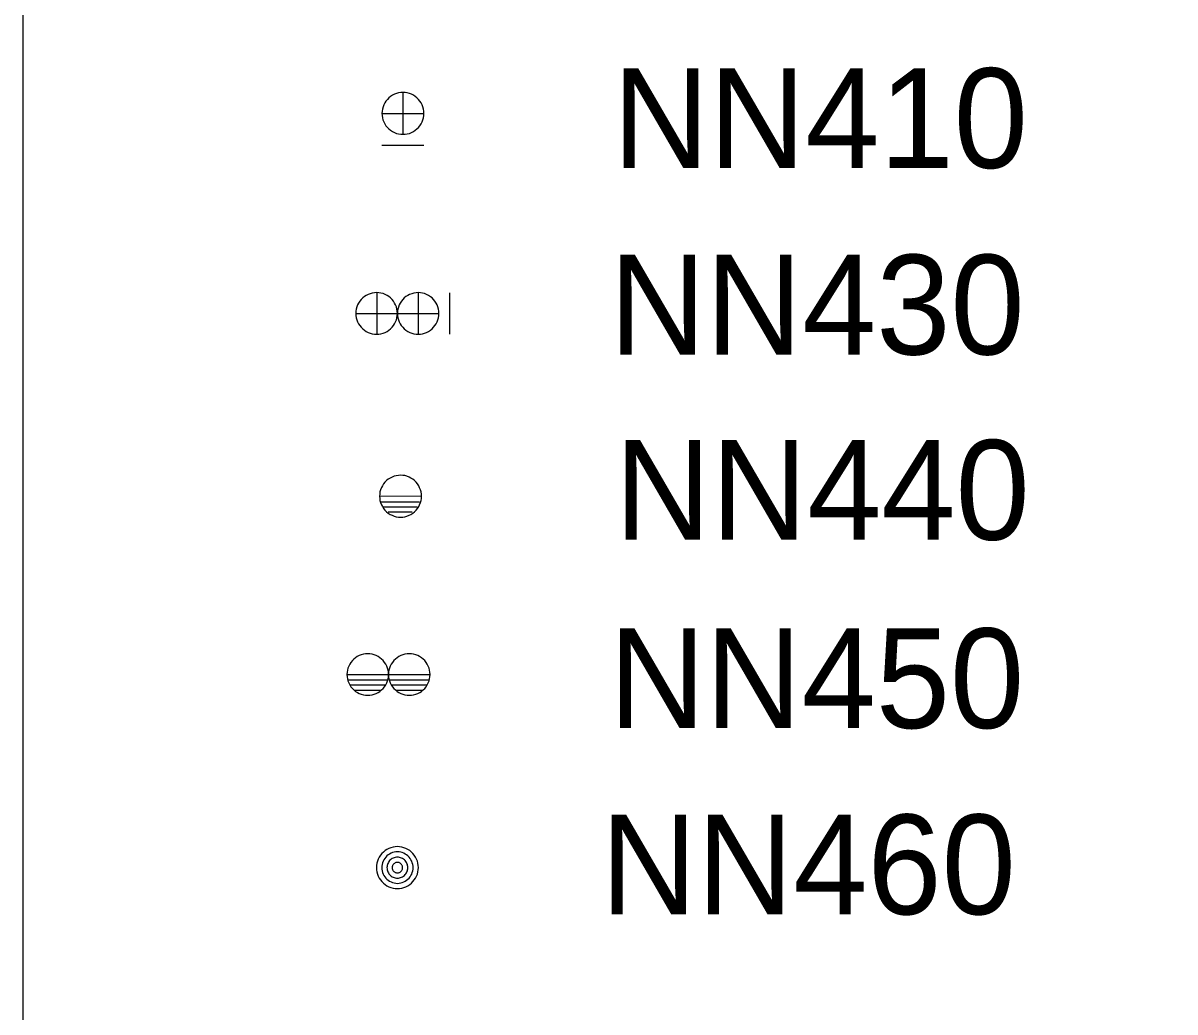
# Model space of a CAD drawing. Extents: x -592825 to -592404, y -1153473 to -1153230.
# Drawn here: x -592679.08 to -592661.76, y -1153367.06 to -1153352.19 of the extents above; entities that cross this region are included whole.
import ezdxf

# ---------------------------------------------------------------- set-up
doc = ezdxf.new("R2010")
doc.units = 0
doc.layers.add('Vrstva 43', color=7, linetype='Continuous')
doc.layers.add('Vrstva 63', color=7, linetype='Continuous')

msp = doc.modelspace()

# ---------------------------------------------------------------- linework, layer by layer
at = {"layer": 'Vrstva 43'}
for points in [[(-592673.055, -1153353.548), (-592673.057, -1153353.515), (-592673.061, -1153353.483), (-592673.07, -1153353.45), (-592673.082, -1153353.42), (-592673.097, -1153353.39), (-592673.115, -1153353.362), (-592673.135, -1153353.337), (-592673.159, -1153353.314), (-592673.185, -1153353.293), (-592673.213, -1153353.275), (-592673.241, -1153353.26), (-592673.273, -1153353.248), (-592673.305, -1153353.24), (-592673.337, -1153353.234), (-592673.37, -1153353.233), (-592673.403, -1153353.235), (-592673.435, -1153353.24), (-592673.467, -1153353.248), (-592673.498, -1153353.26), (-592673.527, -1153353.275), (-592673.555, -1153353.293), (-592673.581, -1153353.314), (-592673.604, -1153353.337), (-592673.625, -1153353.362), (-592673.643, -1153353.391), (-592673.657, -1153353.42), (-592673.669, -1153353.45), (-592673.678, -1153353.483), (-592673.683, -1153353.515), (-592673.685, -1153353.548), (-592673.683, -1153353.581), (-592673.678, -1153353.614), (-592673.67, -1153353.646), (-592673.657, -1153353.676), (-592673.643, -1153353.706), (-592673.625, -1153353.733), (-592673.604, -1153353.759), (-592673.581, -1153353.782), (-592673.555, -1153353.802), (-592673.527, -1153353.82), (-592673.498, -1153353.836), (-592673.467, -1153353.848), (-592673.435, -1153353.856), (-592673.403, -1153353.861), (-592673.37, -1153353.862), (-592673.337, -1153353.861), (-592673.305, -1153353.856), (-592673.273, -1153353.848), (-592673.241, -1153353.836), (-592673.213, -1153353.82), (-592673.185, -1153353.802), (-592673.159, -1153353.782), (-592673.135, -1153353.758), (-592673.115, -1153353.734), (-592673.097, -1153353.705), (-592673.082, -1153353.676), (-592673.07, -1153353.645), (-592673.061, -1153353.613), (-592673.057, -1153353.58), (-592673.055, -1153353.548)], [(-592673.371, -1153353.232), (-592673.371, -1153353.862)], [(-592673.687, -1153353.547), (-592673.056, -1153353.548)], [(-592673.686, -1153354.025), (-592673.056, -1153354.024)], [(-592673.453, -1153356.556), (-592673.455, -1153356.523), (-592673.46, -1153356.49), (-592673.469, -1153356.459), (-592673.481, -1153356.429), (-592673.495, -1153356.4), (-592673.513, -1153356.372), (-592673.534, -1153356.346), (-592673.557, -1153356.324), (-592673.582, -1153356.303), (-592673.609, -1153356.285), (-592673.639, -1153356.27), (-592673.669, -1153356.258), (-592673.701, -1153356.25), (-592673.733, -1153356.246), (-592673.765, -1153356.243), (-592673.799, -1153356.246), (-592673.831, -1153356.25), (-592673.863, -1153356.259), (-592673.893, -1153356.27), (-592673.922, -1153356.286), (-592673.949, -1153356.303), (-592673.975, -1153356.324), (-592673.998, -1153356.347), (-592674.019, -1153356.372), (-592674.036, -1153356.4), (-592674.051, -1153356.428), (-592674.063, -1153356.459), (-592674.071, -1153356.491), (-592674.077, -1153356.523), (-592674.079, -1153356.556), (-592674.077, -1153356.588), (-592674.071, -1153356.62), (-592674.063, -1153356.652), (-592674.051, -1153356.684), (-592674.036, -1153356.712), (-592674.019, -1153356.739), (-592673.998, -1153356.764), (-592673.975, -1153356.788), (-592673.949, -1153356.808), (-592673.921, -1153356.826), (-592673.893, -1153356.841), (-592673.863, -1153356.852), (-592673.831, -1153356.862), (-592673.799, -1153356.866), (-592673.765, -1153356.868), (-592673.733, -1153356.867), (-592673.701, -1153356.862), (-592673.669, -1153356.853), (-592673.639, -1153356.841), (-592673.609, -1153356.826), (-592673.583, -1153356.808), (-592673.557, -1153356.788), (-592673.534, -1153356.765), (-592673.513, -1153356.74), (-592673.495, -1153356.712), (-592673.48, -1153356.683), (-592673.469, -1153356.652), (-592673.46, -1153356.621), (-592673.455, -1153356.589), (-592673.453, -1153356.556)], [(-592673.763, -1153356.246), (-592673.763, -1153356.866)], [(-592672.828, -1153356.556), (-592672.83, -1153356.523), (-592672.835, -1153356.491), (-592672.844, -1153356.459), (-592672.855, -1153356.429), (-592672.87, -1153356.4), (-592672.888, -1153356.372), (-592672.909, -1153356.346), (-592672.931, -1153356.324), (-592672.957, -1153356.304), (-592672.985, -1153356.286), (-592673.014, -1153356.27), (-592673.044, -1153356.258), (-592673.076, -1153356.25), (-592673.108, -1153356.246), (-592673.141, -1153356.243), (-592673.173, -1153356.246), (-592673.205, -1153356.25), (-592673.237, -1153356.259), (-592673.269, -1153356.27), (-592673.297, -1153356.286), (-592673.324, -1153356.303), (-592673.349, -1153356.324), (-592673.373, -1153356.347), (-592673.393, -1153356.372), (-592673.411, -1153356.4), (-592673.427, -1153356.429), (-592673.437, -1153356.46), (-592673.447, -1153356.49), (-592673.451, -1153356.523), (-592673.453, -1153356.556), (-592673.452, -1153356.589), (-592673.447, -1153356.621), (-592673.437, -1153356.652), (-592673.426, -1153356.684), (-592673.411, -1153356.712), (-592673.394, -1153356.74), (-592673.373, -1153356.764), (-592673.35, -1153356.788), (-592673.324, -1153356.808), (-592673.297, -1153356.826), (-592673.267, -1153356.842), (-592673.237, -1153356.852), (-592673.206, -1153356.862), (-592673.173, -1153356.866), (-592673.141, -1153356.868), (-592673.108, -1153356.866), (-592673.075, -1153356.862), (-592673.044, -1153356.853), (-592673.014, -1153356.842), (-592672.985, -1153356.826), (-592672.957, -1153356.809), (-592672.931, -1153356.788), (-592672.909, -1153356.765), (-592672.888, -1153356.74), (-592672.871, -1153356.712), (-592672.855, -1153356.683), (-592672.843, -1153356.652), (-592672.835, -1153356.621), (-592672.83, -1153356.589), (-592672.828, -1153356.556)], [(-592673.143, -1153356.246), (-592673.143, -1153356.866)], [(-592672.671, -1153356.246), (-592672.671, -1153356.866)], [(-592674.079, -1153356.556), (-592672.828, -1153356.556)], [(-592673.091, -1153359.305), (-592673.093, -1153359.272), (-592673.098, -1153359.24), (-592673.107, -1153359.208), (-592673.119, -1153359.177), (-592673.133, -1153359.147), (-592673.151, -1153359.12), (-592673.172, -1153359.094), (-592673.195, -1153359.071), (-592673.221, -1153359.05), (-592673.249, -1153359.032), (-592673.278, -1153359.017), (-592673.309, -1153359.005), (-592673.341, -1153358.996), (-592673.373, -1153358.992), (-592673.407, -1153358.99), (-592673.439, -1153358.992), (-592673.471, -1153358.997), (-592673.503, -1153359.005), (-592673.534, -1153359.018), (-592673.563, -1153359.032), (-592673.591, -1153359.05), (-592673.617, -1153359.071), (-592673.641, -1153359.094), (-592673.661, -1153359.12), (-592673.679, -1153359.147), (-592673.694, -1153359.176), (-592673.705, -1153359.208), (-592673.715, -1153359.239), (-592673.719, -1153359.272), (-592673.721, -1153359.305), (-592673.719, -1153359.338), (-592673.715, -1153359.37), (-592673.705, -1153359.402), (-592673.694, -1153359.434), (-592673.679, -1153359.462), (-592673.661, -1153359.49), (-592673.641, -1153359.516), (-592673.617, -1153359.539), (-592673.591, -1153359.56), (-592673.564, -1153359.578), (-592673.534, -1153359.592), (-592673.503, -1153359.604), (-592673.471, -1153359.613), (-592673.439, -1153359.618), (-592673.406, -1153359.62), (-592673.373, -1153359.618), (-592673.341, -1153359.613), (-592673.309, -1153359.604), (-592673.278, -1153359.592), (-592673.249, -1153359.578), (-592673.221, -1153359.56), (-592673.195, -1153359.538), (-592673.172, -1153359.516), (-592673.151, -1153359.49), (-592673.133, -1153359.462), (-592673.119, -1153359.433), (-592673.107, -1153359.402), (-592673.098, -1153359.37), (-592673.093, -1153359.338), (-592673.091, -1153359.305)], [(-592673.723, -1153359.302), (-592673.092, -1153359.303)], [(-592673.707, -1153359.392), (-592673.122, -1153359.391)], [(-592673.663, -1153359.466), (-592673.156, -1153359.465)], [(-592673.594, -1153359.54), (-592673.23, -1153359.54)], [(-592673.587, -1153361.987), (-592673.589, -1153361.954), (-592673.594, -1153361.922), (-592673.603, -1153361.89), (-592673.614, -1153361.86), (-592673.629, -1153361.83), (-592673.647, -1153361.804), (-592673.667, -1153361.778), (-592673.691, -1153361.755), (-592673.716, -1153361.734), (-592673.743, -1153361.716), (-592673.773, -1153361.702), (-592673.803, -1153361.69), (-592673.835, -1153361.682), (-592673.867, -1153361.676), (-592673.899, -1153361.674), (-592673.933, -1153361.676), (-592673.965, -1153361.682), (-592673.996, -1153361.69), (-592674.027, -1153361.702), (-592674.056, -1153361.716), (-592674.083, -1153361.734), (-592674.109, -1153361.755), (-592674.131, -1153361.778), (-592674.153, -1153361.804), (-592674.17, -1153361.831), (-592674.185, -1153361.86), (-592674.197, -1153361.89), (-592674.205, -1153361.922), (-592674.211, -1153361.954), (-592674.212, -1153361.987), (-592674.211, -1153362.02), (-592674.205, -1153362.052), (-592674.197, -1153362.084), (-592674.185, -1153362.114), (-592674.17, -1153362.144), (-592674.153, -1153362.17), (-592674.131, -1153362.196), (-592674.109, -1153362.219), (-592674.083, -1153362.24), (-592674.055, -1153362.258), (-592674.027, -1153362.272), (-592673.996, -1153362.284), (-592673.965, -1153362.293), (-592673.933, -1153362.298), (-592673.899, -1153362.3), (-592673.867, -1153362.298), (-592673.835, -1153362.293), (-592673.803, -1153362.284), (-592673.773, -1153362.272), (-592673.743, -1153362.258), (-592673.716, -1153362.24), (-592673.691, -1153362.219), (-592673.667, -1153362.196), (-592673.647, -1153362.17), (-592673.629, -1153362.143), (-592673.614, -1153362.114), (-592673.603, -1153362.084), (-592673.594, -1153362.052), (-592673.589, -1153362.02), (-592673.587, -1153361.987)], [(-592672.962, -1153361.987), (-592672.964, -1153361.954), (-592672.969, -1153361.922), (-592672.977, -1153361.89), (-592672.989, -1153361.86), (-592673.004, -1153361.83), (-592673.022, -1153361.804), (-592673.043, -1153361.778), (-592673.065, -1153361.755), (-592673.091, -1153361.734), (-592673.119, -1153361.716), (-592673.147, -1153361.702), (-592673.178, -1153361.69), (-592673.209, -1153361.682), (-592673.242, -1153361.676), (-592673.275, -1153361.674), (-592673.307, -1153361.676), (-592673.339, -1153361.682), (-592673.371, -1153361.69), (-592673.402, -1153361.702), (-592673.431, -1153361.716), (-592673.458, -1153361.734), (-592673.483, -1153361.755), (-592673.507, -1153361.778), (-592673.527, -1153361.804), (-592673.545, -1153361.831), (-592673.56, -1153361.86), (-592673.571, -1153361.89), (-592673.581, -1153361.922), (-592673.585, -1153361.954), (-592673.587, -1153361.987), (-592673.585, -1153362.02), (-592673.581, -1153362.052), (-592673.571, -1153362.084), (-592673.56, -1153362.114), (-592673.545, -1153362.144), (-592673.527, -1153362.17), (-592673.507, -1153362.196), (-592673.483, -1153362.219), (-592673.458, -1153362.24), (-592673.431, -1153362.258), (-592673.401, -1153362.272), (-592673.371, -1153362.284), (-592673.339, -1153362.293), (-592673.307, -1153362.298), (-592673.275, -1153362.3), (-592673.242, -1153362.298), (-592673.209, -1153362.293), (-592673.178, -1153362.284), (-592673.147, -1153362.272), (-592673.118, -1153362.258), (-592673.091, -1153362.24), (-592673.065, -1153362.219), (-592673.043, -1153362.196), (-592673.022, -1153362.17), (-592673.004, -1153362.143), (-592672.989, -1153362.114), (-592672.977, -1153362.084), (-592672.969, -1153362.052), (-592672.964, -1153362.02), (-592672.962, -1153361.987)], [(-592674.212, -1153361.987), (-592672.962, -1153361.987)], [(-592674.202, -1153362.066), (-592673.597, -1153362.066)], [(-592673.577, -1153362.066), (-592672.972, -1153362.066)], [(-592674.167, -1153362.144), (-592673.631, -1153362.144)], [(-592674.103, -1153362.223), (-592673.695, -1153362.223)], [(-592673.543, -1153362.144), (-592673.006, -1153362.144)], [(-592673.479, -1153362.223), (-592673.071, -1153362.223)], [(-592673.138, -1153364.892), (-592673.14, -1153364.858), (-592673.145, -1153364.826), (-592673.153, -1153364.794), (-592673.165, -1153364.764), (-592673.181, -1153364.734), (-592673.199, -1153364.706), (-592673.219, -1153364.68), (-592673.243, -1153364.658), (-592673.268, -1153364.636), (-592673.295, -1153364.618), (-592673.325, -1153364.604), (-592673.356, -1153364.592), (-592673.387, -1153364.584), (-592673.42, -1153364.578), (-592673.453, -1153364.576), (-592673.486, -1153364.578), (-592673.519, -1153364.584), (-592673.551, -1153364.592), (-592673.581, -1153364.604), (-592673.611, -1153364.618), (-592673.638, -1153364.636), (-592673.664, -1153364.658), (-592673.687, -1153364.68), (-592673.708, -1153364.706), (-592673.726, -1153364.734), (-592673.741, -1153364.764), (-592673.753, -1153364.794), (-592673.761, -1153364.826), (-592673.767, -1153364.858), (-592673.768, -1153364.892), (-592673.767, -1153364.924), (-592673.761, -1153364.957), (-592673.753, -1153364.989), (-592673.741, -1153365.02), (-592673.726, -1153365.049), (-592673.708, -1153365.076), (-592673.687, -1153365.102), (-592673.664, -1153365.126), (-592673.638, -1153365.146), (-592673.611, -1153365.164), (-592673.581, -1153365.179), (-592673.551, -1153365.191), (-592673.519, -1153365.2), (-592673.486, -1153365.205), (-592673.453, -1153365.206), (-592673.42, -1153365.204), (-592673.387, -1153365.2), (-592673.356, -1153365.191), (-592673.325, -1153365.179), (-592673.295, -1153365.164), (-592673.268, -1153365.146), (-592673.243, -1153365.126), (-592673.219, -1153365.102), (-592673.199, -1153365.076), (-592673.181, -1153365.049), (-592673.165, -1153365.02), (-592673.153, -1153364.988), (-592673.145, -1153364.957), (-592673.14, -1153364.924), (-592673.138, -1153364.892)], [(-592673.217, -1153364.892), (-592673.218, -1153364.867), (-592673.222, -1153364.842), (-592673.229, -1153364.818), (-592673.237, -1153364.796), (-592673.249, -1153364.774), (-592673.262, -1153364.752), (-592673.277, -1153364.734), (-592673.295, -1153364.716), (-592673.315, -1153364.7), (-592673.335, -1153364.687), (-592673.357, -1153364.676), (-592673.38, -1153364.666), (-592673.404, -1153364.66), (-592673.429, -1153364.656), (-592673.453, -1153364.655), (-592673.477, -1153364.656), (-592673.502, -1153364.66), (-592673.526, -1153364.666), (-592673.549, -1153364.676), (-592673.571, -1153364.687), (-592673.592, -1153364.7), (-592673.611, -1153364.716), (-592673.629, -1153364.734), (-592673.644, -1153364.752), (-592673.657, -1153364.774), (-592673.669, -1153364.796), (-592673.678, -1153364.818), (-592673.684, -1153364.842), (-592673.688, -1153364.867), (-592673.689, -1153364.892), (-592673.688, -1153364.916), (-592673.684, -1153364.94), (-592673.678, -1153364.964), (-592673.669, -1153364.988), (-592673.657, -1153365.01), (-592673.644, -1153365.03), (-592673.629, -1153365.05), (-592673.611, -1153365.067), (-592673.592, -1153365.082), (-592673.571, -1153365.096), (-592673.549, -1153365.107), (-592673.526, -1153365.116), (-592673.502, -1153365.122), (-592673.477, -1153365.126), (-592673.453, -1153365.128), (-592673.429, -1153365.126), (-592673.404, -1153365.122), (-592673.38, -1153365.116), (-592673.357, -1153365.107), (-592673.335, -1153365.096), (-592673.315, -1153365.082), (-592673.295, -1153365.067), (-592673.277, -1153365.05), (-592673.262, -1153365.03), (-592673.249, -1153365.01), (-592673.237, -1153364.988), (-592673.229, -1153364.964), (-592673.222, -1153364.94), (-592673.218, -1153364.916), (-592673.217, -1153364.892)], [(-592673.295, -1153364.892), (-592673.297, -1153364.875), (-592673.299, -1153364.858), (-592673.303, -1153364.843), (-592673.309, -1153364.828), (-592673.317, -1153364.813), (-592673.325, -1153364.799), (-592673.336, -1153364.786), (-592673.347, -1153364.774), (-592673.361, -1153364.764), (-592673.375, -1153364.755), (-592673.389, -1153364.748), (-592673.405, -1153364.742), (-592673.421, -1153364.738), (-592673.437, -1153364.735), (-592673.453, -1153364.734), (-592673.469, -1153364.735), (-592673.486, -1153364.738), (-592673.502, -1153364.742), (-592673.517, -1153364.748), (-592673.532, -1153364.755), (-592673.545, -1153364.764), (-592673.559, -1153364.774), (-592673.57, -1153364.786), (-592673.581, -1153364.799), (-592673.589, -1153364.813), (-592673.597, -1153364.828), (-592673.603, -1153364.843), (-592673.607, -1153364.858), (-592673.609, -1153364.875), (-592673.611, -1153364.892), (-592673.609, -1153364.908), (-592673.607, -1153364.924), (-592673.603, -1153364.94), (-592673.597, -1153364.956), (-592673.589, -1153364.97), (-592673.581, -1153364.984), (-592673.57, -1153364.997), (-592673.559, -1153365.008), (-592673.545, -1153365.019), (-592673.532, -1153365.028), (-592673.517, -1153365.035), (-592673.502, -1153365.041), (-592673.486, -1153365.046), (-592673.469, -1153365.048), (-592673.453, -1153365.049), (-592673.437, -1153365.048), (-592673.421, -1153365.046), (-592673.405, -1153365.041), (-592673.389, -1153365.035), (-592673.375, -1153365.028), (-592673.361, -1153365.019), (-592673.347, -1153365.008), (-592673.336, -1153364.997), (-592673.325, -1153364.984), (-592673.317, -1153364.97), (-592673.309, -1153364.956), (-592673.303, -1153364.94), (-592673.299, -1153364.924), (-592673.297, -1153364.908), (-592673.295, -1153364.892)], [(-592673.375, -1153364.892), (-592673.375, -1153364.884), (-592673.376, -1153364.875), (-592673.378, -1153364.867), (-592673.381, -1153364.86), (-592673.385, -1153364.852), (-592673.389, -1153364.845), (-592673.395, -1153364.838), (-592673.401, -1153364.833), (-592673.407, -1153364.828), (-592673.414, -1153364.824), (-592673.421, -1153364.82), (-592673.429, -1153364.816), (-592673.437, -1153364.814), (-592673.445, -1153364.813), (-592673.453, -1153364.813), (-592673.461, -1153364.813), (-592673.469, -1153364.814), (-592673.477, -1153364.816), (-592673.485, -1153364.82), (-592673.493, -1153364.824), (-592673.499, -1153364.828), (-592673.506, -1153364.833), (-592673.511, -1153364.838), (-592673.517, -1153364.845), (-592673.521, -1153364.852), (-592673.525, -1153364.86), (-592673.528, -1153364.867), (-592673.53, -1153364.875), (-592673.531, -1153364.884), (-592673.532, -1153364.892), (-592673.531, -1153364.9), (-592673.53, -1153364.908), (-592673.528, -1153364.916), (-592673.525, -1153364.924), (-592673.521, -1153364.931), (-592673.517, -1153364.938), (-592673.511, -1153364.944), (-592673.506, -1153364.95), (-592673.499, -1153364.955), (-592673.493, -1153364.96), (-592673.485, -1153364.964), (-592673.477, -1153364.966), (-592673.469, -1153364.968), (-592673.461, -1153364.97), (-592673.453, -1153364.97), (-592673.445, -1153364.97), (-592673.437, -1153364.968), (-592673.429, -1153364.966), (-592673.421, -1153364.964), (-592673.414, -1153364.96), (-592673.407, -1153364.955), (-592673.401, -1153364.95), (-592673.395, -1153364.944), (-592673.389, -1153364.938), (-592673.385, -1153364.931), (-592673.381, -1153364.924), (-592673.378, -1153364.916), (-592673.376, -1153364.908), (-592673.375, -1153364.9), (-592673.375, -1153364.892)]]:
    msp.add_lwpolyline(points, dxfattribs=at)
at = {"layer": 'Vrstva 63'}
msp.add_lwpolyline([(-592679.084, -1153338.599), (-592600.649, -1153338.599), (-592600.649, -1153436.347), (-592679.084, -1153436.347)], close=True, dxfattribs=at)

# ---------------------------------------------------------------- texts
for s, p in [('NN410', (-592670.213, -1153354.368)), ('NN430', (-592670.262, -1153357.174)), ('NN440', (-592670.185, -1153359.96)), ('NN450', (-592670.269, -1153362.793)), ('NN460', (-592670.395, -1153365.593))]:
    msp.add_text(s, height=1.5, dxfattribs=at).set_placement(p)

doc.saveas('drawing.dxf')
